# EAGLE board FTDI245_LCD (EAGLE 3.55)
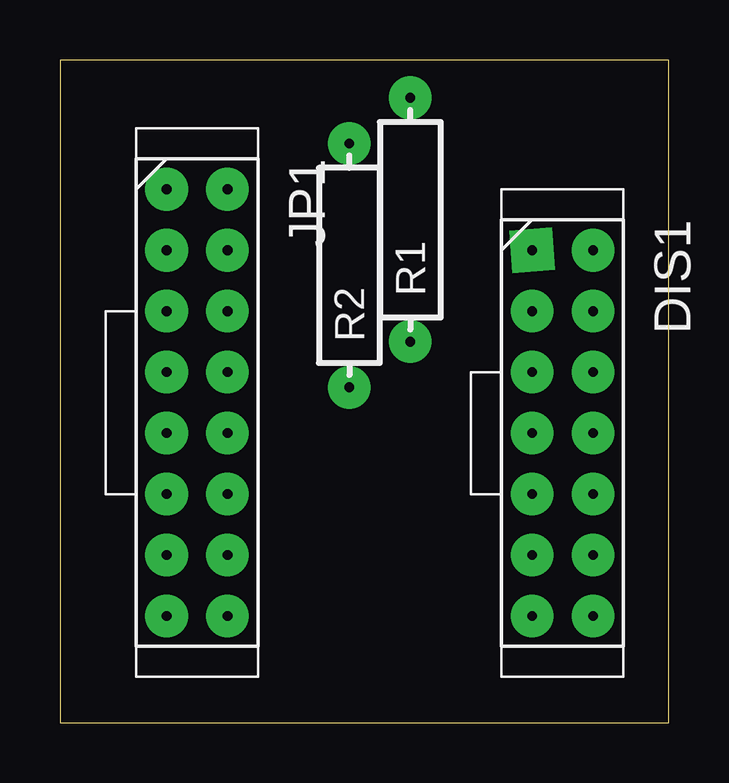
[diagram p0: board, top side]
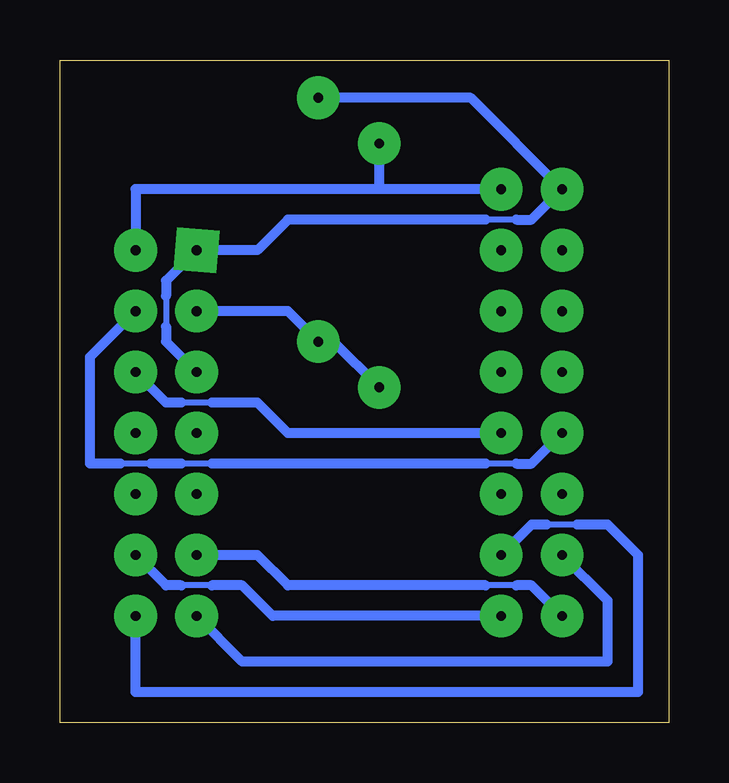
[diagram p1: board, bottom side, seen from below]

Size 25.38 x 27.61 mm. Coordinates in mm from the lower left corner, seen from the top.
Outline: 0,0 25.38,0 25.38,27.61 0,27.61 0,0
Copper layers used: Bottom

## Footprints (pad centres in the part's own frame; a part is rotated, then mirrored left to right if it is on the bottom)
7 = drill 0.406 pad 1.778 square:  0,0 | drill 0.406 pad 1.778 round:  2.54,0;  5.08,0;  7.62,0;  10.16,0;  10.16,2.54;  7.62,2.54;  5.08,2.54;  2.54,2.54;  0,2.54;  12.7,0;  12.7,2.54;  15.24,0;  15.24,2.54
8 = drill 0.406 pad 1.778 round:  -8.89,-1.27;  -6.35,-1.27;  -3.81,-1.27;  -1.27,-1.27;  1.27,-1.27;  1.27,1.27;  -1.27,1.27;  -3.81,1.27;  -6.35,1.27;  -8.89,1.27;  3.81,-1.27;  3.81,1.27;  6.35,-1.27;  6.35,1.27;  8.89,-1.27;  8.89,1.27
S04 = drill 0.406 pad 1.778 round:  -5.08,0;  5.08,0

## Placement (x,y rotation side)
DIS1  2X7  [7]  19.68,19.68 270 top
JP1  PINHD-2X8  [8]  5.71,13.34 270 top
R1  820  [S04]  14.61,20.95 90 top
R2  10k  [S04]  12.06,19.05 90 top

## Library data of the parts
DIS1 R1 R2 = holg_plt
JP1 = PINHEAD

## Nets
+5V: DIS1. JP1. R2.
/RD: JP1.
/RXF: JP1.
/TXE: JP1.
D0: DIS1. JP1.
D1: DIS1. JP1.
D2: DIS1. JP1.
D3: DIS1. JP1.
D4: JP1.
D5: JP1.
D6: DIS1. JP1.
D7: DIS1. JP1.
GND: DIS1. JP1. R1.
N$9: DIS1. R1. R2.
SI/WU: JP1.
WR: JP1.

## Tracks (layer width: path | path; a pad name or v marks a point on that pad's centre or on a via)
+5V
  Bottom 0.406: 6.99,22.23 12.06,22.23 | 12.06,22.23 22.23,22.23 22.23,19.68 | 12.06,22.23 R2.
D0
  Bottom 0.254: 6.35,5.71 7.62,5.71
  Bottom 0.406: 19.68,6.99 17.14,6.99 15.88,5.71 7.62,5.71 | 4.45,4.45 5.71,5.71 6.35,5.71
D1
  Bottom 0.254: 19.05,5.71 20.32,5.71
  Bottom 0.406: 22.23,6.99 20.95,5.71 20.32,5.71 | JP1. 16.51,4.45 17.78,5.71 19.05,5.71
D2
  Bottom 0.406: 19.68,4.45 17.78,2.54 2.54,2.54 2.54,5.08 4.45,6.99
D3
  Bottom 0.254: 3.81,8.26 5.08,8.26
  Bottom 0.406: 6.99,6.99 5.71,8.26 5.08,8.26 | DIS1. 22.23,1.27 1.27,1.27 1.27,6.99 2.54,8.26 3.81,8.26
D6
  Bottom 0.254: 21.59,10.79 22.86,10.79 | 6.35,10.79 7.62,10.79 | 19.05,10.79 20.32,10.79
  Bottom 0.406: 4.45,12.06 5.71,10.79 6.35,10.79 | 22.23,17.14 24.13,15.24 24.13,10.79 22.86,10.79 | 7.62,10.79 19.05,10.79 | 20.32,10.79 21.59,10.79
D7
  Bottom 0.254: 19.05,13.34 20.32,13.34
  Bottom 0.406: 6.99,12.06 15.88,12.06 17.14,13.34 19.05,13.34 | 22.23,14.61 20.95,13.34 20.32,13.34
GND
  Bottom 0.254: 6.35,20.95 7.62,20.95 | 20.95,17.78 20.95,16.51
  Bottom 0.406: 6.35,20.95 5.71,20.95 4.45,22.23 8.26,26.04 R1. | 7.62,20.95 15.88,20.95 17.14,19.68 19.68,19.68 20.95,18.41 20.95,17.78 | 19.68,14.61 20.95,15.88 20.95,16.51
N$9
  Bottom 0.406: 19.68,17.14 15.88,17.14 14.61,15.88 13.97,15.88 12.06,13.97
